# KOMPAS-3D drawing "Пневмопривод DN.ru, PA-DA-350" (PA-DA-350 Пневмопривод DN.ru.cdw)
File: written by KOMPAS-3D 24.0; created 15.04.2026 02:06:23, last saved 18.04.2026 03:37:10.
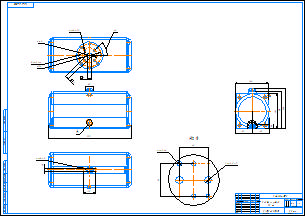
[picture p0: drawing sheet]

Document properties: Автор: DN.ru; Форматы листов документа: A1; Полное имя файла: PA-DA-350 Пневмопривод DN.ru.m3d; Масса: 186; Наименование: Пневмопривод DN.ru; Количество листов документа: 1; Примечание: D290-00303

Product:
- Part/product: Пневмопривод DN.ru  | designation PA-DA-350
    Масса: 186
    Раздел спецификации: Прочие изделия
    Примечание: D290-00303

Views: Вид 1, Вид:1, Проекционный вид 2, Проекционный вид 5, Местный разрез 1, Выносной элемент 6, Выносной элемент А, Выносной элемент
Referenced files in C:\Работа\PA-DA-х Пневмопривод DN.ru\052\: PA-DA-052 Пневмопривод DN.ru.m3d
Referenced files in C:\Работа\PA-DA-х Пневмопривод DN.ru\350\: PA-DA-350 Пневмопривод DN.ru.m3d
Referenced files in C:\Работа\PA-DA-х Пневмопривод DN.ru\160\: PA-DA-160 Пневмопривод DN.ru.m3d
Referenced files in C:\Program Files\ASCON\KOMPAS-3D v24\Templates\: Чертеж_DN.ru.cdt
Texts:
  objid
  viewid
  PA-DA-350
  Чертеж_DN.ru.cdt
  Пневмопривод
  Пневмопривод DN.ru
  PA-DA-350 Пневмопривод DN.ru
Dimensions and other numbers on the sheet: 0; 3; 2; 4; 80; 608; 920; 46; 165; 4 отв.; 20; 254; 8 отв.; 16; 6; 365; 190; 195; 383; 410; 440; 50; 7; 1; 2 отв.; 40; 45; 1:4; 186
